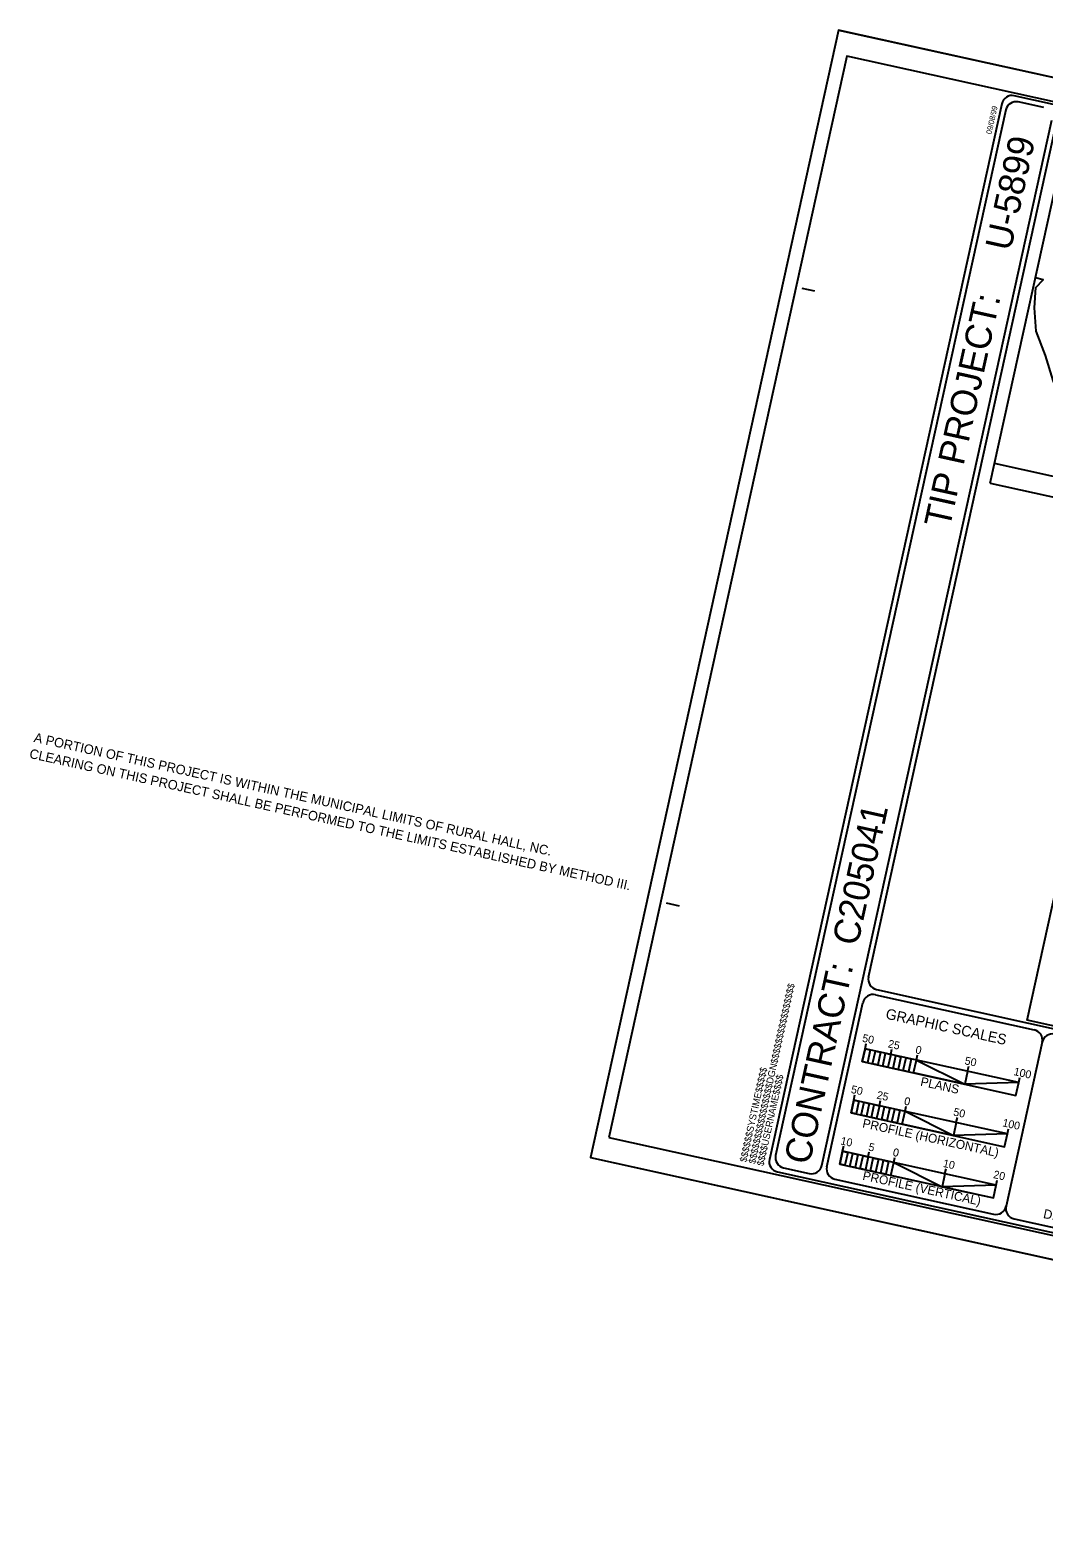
# Model space of a CAD drawing. Extents: x 1609449 to 1623942, y 894240 to 902860.
# Drawn here: x 1609449 to 1615249, y 894240 to 902860 of the extents above; entities that cross this region are included whole.
import ezdxf

# ---------------------------------------------------------------- set-up
doc = ezdxf.new("R2010")
doc.units = 0
for name, color, linetype in [('Exist Boundary Political City Limit New', 7, 'Continuous'), ('Prop DSN Text', 7, 'Continuous'), ('Scratch_Level_0', 7, 'Continuous'), ('Scratch_Level_1', 7, 'Continuous'), ('Sheet Cutting Line CELL', 7, 'Continuous'), ('Sheet Data Field CELL', 7, 'Continuous'), ('Sheet Plot Border Inside CELL', 7, 'Continuous'), ('Sheet Plot Border Outside CELL', 7, 'Continuous'), ('Sheet Title CELL', 7, 'Continuous')]:
    doc.layers.add(name, color=color, linetype=linetype)

msp = doc.modelspace()

# ---------------------------------------------------------------- linework, layer by layer
at = {"layer": 'Exist Boundary Political City Limit New'}
for points in [[(1615203.6, 901388.9), (1615244.8, 901433.1), (1615200.3, 901442.9)], [(1615781.4, 900355.3), (1615647.1, 900392.5), (1615527.4, 900442.4), (1615460.2, 900501), (1615389.2, 900616.1), (1615369.7, 900679.2), (1615303.1, 900856.7), (1615259.2, 901000.3), (1615204.1, 901139.3), (1615195.1, 901271.4), (1615203.6, 901388.9)]]:
    msp.add_lwpolyline(points, dxfattribs=at)
at = {"layer": 'Prop DSN Text'}
for q in [(1614966.7, 900382.4), (1616581.2, 899908.4)]:
    msp.add_line((1614941.8, 900269.6), q, dxfattribs=at)
msp.add_lwpolyline([(1617019.1, 901896.3), (1616606, 900021.2), (1614966.7, 900382.4), (1615379.8, 902257.5)], close=True, dxfattribs=at)
at = {"layer": 'Scratch_Level_0'}
msp.add_lwpolyline([(1615937.3, 900755.3), (1622890.3, 899223.5), (1622107.1, 895668.6), (1615154.1, 897200.4)], close=True, dxfattribs=at)
at = {"layer": 'Scratch_Level_1'}
msp.add_lwpolyline([(1615937.3, 900755.3), (1622890.3, 899223.5), (1622107.1, 895668.6), (1615154.1, 897200.4)], close=True, dxfattribs=at)
at = {"layer": 'Sheet Cutting Line CELL'}
for p, q in [((1614074.8, 902859.7), (1612654.8, 896414.4)), ((1614074.8, 902859.7), (1623942.2, 900685.8)), ((1612654.8, 896414.4), (1622522.2, 894240.5))]:
    msp.add_line(p, q, dxfattribs=at)
at = {"layer": 'Sheet Data Field CELL'}
for p, q in [((1614226.5, 897036.4), (1614233, 897065.7)), ((1614373, 897004.1), (1614379.5, 897033.4)), ((1614812.5, 896907.4), (1614818.9, 896936.6)), ((1615105.4, 896842.7), (1615111.9, 896872.1)), ((1613665.7, 896345.3), (1613665.7, 896345.3))]:
    msp.add_line(p, q, dxfattribs=at)
at = {"layer": 'Sheet Plot Border Inside CELL'}
msp.add_lwpolyline([(1612759.9, 896529.1), (1622524.8, 894377.7), (1623886.8, 900560.1), (1614122, 902711.4)], close=True, dxfattribs=at)
at = {"layer": 'Sheet Plot Border Outside CELL'}
msp.add_lwpolyline([(1623942.2, 900685.8), (1614074.8, 902859.7), (1612654.8, 896414.4), (1622522.2, 894240.5)], close=True, dxfattribs=at)
at = {"layer": 'Sheet Title CELL'}
for p, q in [((1613977.9, 896368.6), (1615294.7, 902345.3)), ((1614246.1, 897446.2), (1615324, 902338.8)), ((1613863.7, 901385.6), (1613936.9, 901369.5)), ((1613089.1, 897869.9), (1613162.4, 897853.9)), ((1614291.7, 897374.7), (1622612.2, 895541.6)), ((1614007.3, 896362.1), (1614213.8, 897299.7)), ((1614285.3, 897345.3), (1615193.5, 897145.3)), ((1614226.4, 897036.4), (1614210.3, 896963.1)), ((1614226.4, 897036.4), (1614232.9, 897065.6)), ((1614226.4, 897036.4), (1614226.4, 897036.4)), ((1615105.4, 896842.8), (1614226.4, 897036.4)), ((1614232.9, 897065.6), (1614232.9, 897065.6)), ((1614372.9, 897004), (1614379.4, 897033.4)), ((1615239.2, 897073.8), (1615032.6, 896136.2)), ((1614210.3, 896963.1), (1615089.2, 896769.4)), ((1614431.5, 896991.2), (1614415.4, 896918)), ((1614519.4, 896971.8), (1614525.9, 897001.1)), ((1614812.4, 896907.3), (1614818.8, 896936.5)), ((1614812.4, 896907.3), (1614796.3, 896834.1)), ((1615089.2, 896769.4), (1615105.4, 896842.8)), ((1615105.4, 896842.8), (1615111.8, 896872.1)), ((1614161.9, 896743.3), (1614168.3, 896772.7)), ((1614168.3, 896772.7), (1614168.3, 896772.7)), ((1614161.9, 896743.3), (1614145.8, 896670.2)), ((1614145.8, 896670.2), (1615024.7, 896476.5)), ((1614161.9, 896743.3), (1614161.9, 896743.3)), ((1615040.8, 896549.8), (1614161.9, 896743.3)), ((1614308.4, 896711.1), (1614314.8, 896740.4)), ((1614367, 896698.2), (1614350.8, 896625)), ((1614454.9, 896678.9), (1614461.3, 896708.1)), ((1614747.8, 896614.3), (1614731.7, 896541.1)), ((1614747.8, 896614.3), (1614754.3, 896643.6)), ((1615040.8, 896549.8), (1615047.3, 896579.1)), ((1615024.7, 896476.5), (1615040.8, 896549.8)), ((1614097.4, 896450.4), (1614081.2, 896377.2)), ((1614097.4, 896450.4), (1614103.8, 896479.7)), ((1614097.4, 896450.4), (1614097.4, 896450.4)), ((1614976.3, 896256.8), (1614097.4, 896450.4)), ((1614103.8, 896479.7), (1614103.8, 896479.7)), ((1614243.8, 896418.2), (1614250.3, 896447.4)), ((1614302.4, 896405.2), (1614286.3, 896331.9)), ((1614390.3, 896385.9), (1614396.8, 896415.1)), ((1613665.6, 896345.3), (1613665.6, 896345.3)), ((1614081.2, 896377.2), (1614960.1, 896183.6)), ((1614683.3, 896321.3), (1614667.1, 896248)), ((1614683.3, 896321.3), (1614689.7, 896350.6)), ((1614960.1, 896183.6), (1614976.3, 896256.8)), ((1614976.3, 896256.8), (1614982.7, 896286))]:
    msp.add_line(p, q, dxfattribs=at)
for points in [[(1615008.2, 902439.1), (1613678.5, 896403.9)], [(1623751.8, 900574.2), (1615079.6, 902484.8)], [(1615249, 902416.7), (1615102.5, 902449.1)], [(1615031.1, 902403.4), (1613714.3, 896426.7)], [(1613724.2, 896332.3), (1622396.2, 894421.7)], [(1613759.9, 896355.2), (1613906.4, 896322.9)], [(1614052.9, 896290.6), (1614961.1, 896090.6)], [(1615078.3, 896064.7), (1615928, 895877.6)]]:
    msp.add_lwpolyline(points, dxfattribs=at)
for points in [[(1614226.4, 897036.4), (1614255.7, 897029.9), (1614239.6, 896956.7), (1614210.3, 896963.1)], [(1614285, 897023.5), (1614314.3, 897017), (1614298.2, 896943.7), (1614269, 896950.1)], [(1614343.6, 897010.5), (1614372.9, 897004), (1614356.8, 896930.9), (1614327.5, 896937.3)], [(1614402.2, 896997.6), (1614431.5, 896991.2), (1614415.4, 896918), (1614386.1, 896924.4)], [(1614460.8, 896984.8), (1614490.1, 896978.3), (1614474, 896905), (1614444.7, 896911.5)], [(1614519.4, 896971.8), (1614796.3, 896834.1), (1614503.3, 896898.5)], [(1615105.4, 896842.8), (1614796.3, 896834.1), (1615089.2, 896769.4)], [(1614161.9, 896743.3), (1614191.2, 896737), (1614175.1, 896663.7), (1614145.8, 896670.2)], [(1614220.5, 896730.5), (1614249.8, 896724.1), (1614233.7, 896650.7), (1614204.4, 896657.3)], [(1614279.1, 896717.6), (1614308.4, 896711.1), (1614292.2, 896637.9), (1614262.9, 896644.3)], [(1614337.7, 896704.6), (1614367, 896698.2), (1614350.8, 896625), (1614321.5, 896631.4)], [(1614396.3, 896691.8), (1614425.6, 896685.3), (1614409.4, 896612.1), (1614380.1, 896618.5)], [(1614454.9, 896678.9), (1614731.7, 896541.1), (1614438.7, 896605.6)], [(1615040.8, 896549.8), (1614731.7, 896541.1), (1615024.7, 896476.5)], [(1614097.4, 896450.4), (1614126.6, 896443.9), (1614110.5, 896370.7), (1614081.2, 896377.2)], [(1614155.9, 896437.5), (1614185.2, 896431.1), (1614169.1, 896357.8), (1614139.8, 896364.3)], [(1614214.5, 896424.6), (1614243.8, 896418.2), (1614227.7, 896344.9), (1614198.4, 896351.4)], [(1614273.2, 896411.6), (1614302.4, 896405.2), (1614286.3, 896331.9), (1614257, 896338.5)], [(1614331.7, 896398.7), (1614361, 896392.4), (1614344.9, 896319.1), (1614315.6, 896325.6)], [(1614390.3, 896385.9), (1614667.1, 896248), (1614374.2, 896312.7)], [(1614976.3, 896256.8), (1614667.1, 896248), (1614960.1, 896183.6)]]:
    msp.add_lwpolyline(points, close=True, dxfattribs=at)
for centre, start, end in [((1615066.8, 902426.5), 77.57547, 167.57547), ((1615089.7, 902390.7), 77.57547, 167.57547), ((1614304.7, 897433.5), 167.57547, 257.57547), ((1614272.5, 897287), 77.57547, 167.57547), ((1615180.7, 897086.9), 347.57547, 77.57547), ((1615297.9, 897061.1), 77.57547, 167.57547), ((1613737.2, 896391.2), 167.57547, 257.57547), ((1613772.9, 896414.1), 167.57547, 257.57547), ((1613919.4, 896381.8), 257.57547, 347.57547), ((1614065.9, 896349.5), 167.57547, 257.57547), ((1614974.1, 896149.4), 257.57547, 347.57547), ((1615091.3, 896123.6), 167.57547, 257.57547)]:
    msp.add_arc(centre, 60, start, end, dxfattribs=at)

# ---------------------------------------------------------------- texts
at = {"layer": 'Sheet Data Field CELL'}
for s, height, p in [('A PORTION OF THIS PROJECT IS WITHIN THE MUNICIPAL LIMITS OF RURAL HALL, NC.', 54.45, (1609467.1, 898791.1)), ('CLEARING ON THIS PROJECT SHALL BE PERFORMED TO THE LIMITS ESTABLISHED BY METHOD III.', 54.45, (1609441.7, 898699.4)), ('50', 45, (1614206.8, 897077.6)), ('25', 45, (1614354.2, 897045.1)), ('50', 45, (1614792.8, 896948.5)), ('100', 45, (1615073.6, 896886.7)), ('50', 45, (1614142.3, 896784.6)), ('25', 45, (1614289.7, 896752.2)), ('50', 45, (1614728.2, 896655.5)), ('100', 45, (1615009.1, 896593.7)), ('10', 45, (1614083, 896490.5)), ('5', 45, (1614242.5, 896455.4)), ('10', 45, (1614668.9, 896361.5)), ('20', 45, (1614956.7, 896298)), ('DIVISION TIER', 52.5, (1615242.2, 896069.9))]:
    msp.add_text(s, height=height, rotation=347.57547, dxfattribs=at).set_placement(p)
at = {"layer": 'Sheet Title CELL'}
for s, height, rotation, p in [('09/08/99', 31.5, 77.57547, (1614949.3, 902262.4)), ('U-5899', 150, 77.57547, (1615058.8, 901592)), ('TIP PROJECT:', 150, 77.57547, (1614709.6, 900007.2)), ('CONTRACT:  C205041', 150, 77.57547, (1613907.9, 896368.4)), ('$$$$$$$$$$$$$$$$DGN$$$$$$$$$$$$$$$$', 39.375, 77.57547, (1613597.3, 896375.8)), ('GRAPHIC SCALES', 59.998, 347.57547, (1614340.2, 897209.2)), ('0', 45, 347.57547, (1614511.2, 897011.4)), ('$$$$$$SYSTIME$$$$$', 39.375, 77.57547, (1613547.2, 896385.3)), ('$$$$USERNAME$$$$', 39.375, 77.57547, (1613645.1, 896364.1)), ('PLANS', 51, 347.57547, (1614539.5, 896826)), ('0', 45, 347.57547, (1614446.5, 896717.6)), ('0', 45, 347.57547, (1614446.7, 896718.5)), ('PROFILE (HORIZONTAL)', 50.998, 347.57547, (1614207.8, 896587.9)), ('0', 45, 347.57547, (1614382, 896424.6)), ('0', 45, 347.57547, (1614382.1, 896425.5)), ('PROFILE (VERTICAL)', 50.998, 347.57547, (1614208.7, 896288.2))]:
    msp.add_text(s, height=height, rotation=rotation, dxfattribs=at).set_placement(p)

doc.saveas('drawing.dxf')
